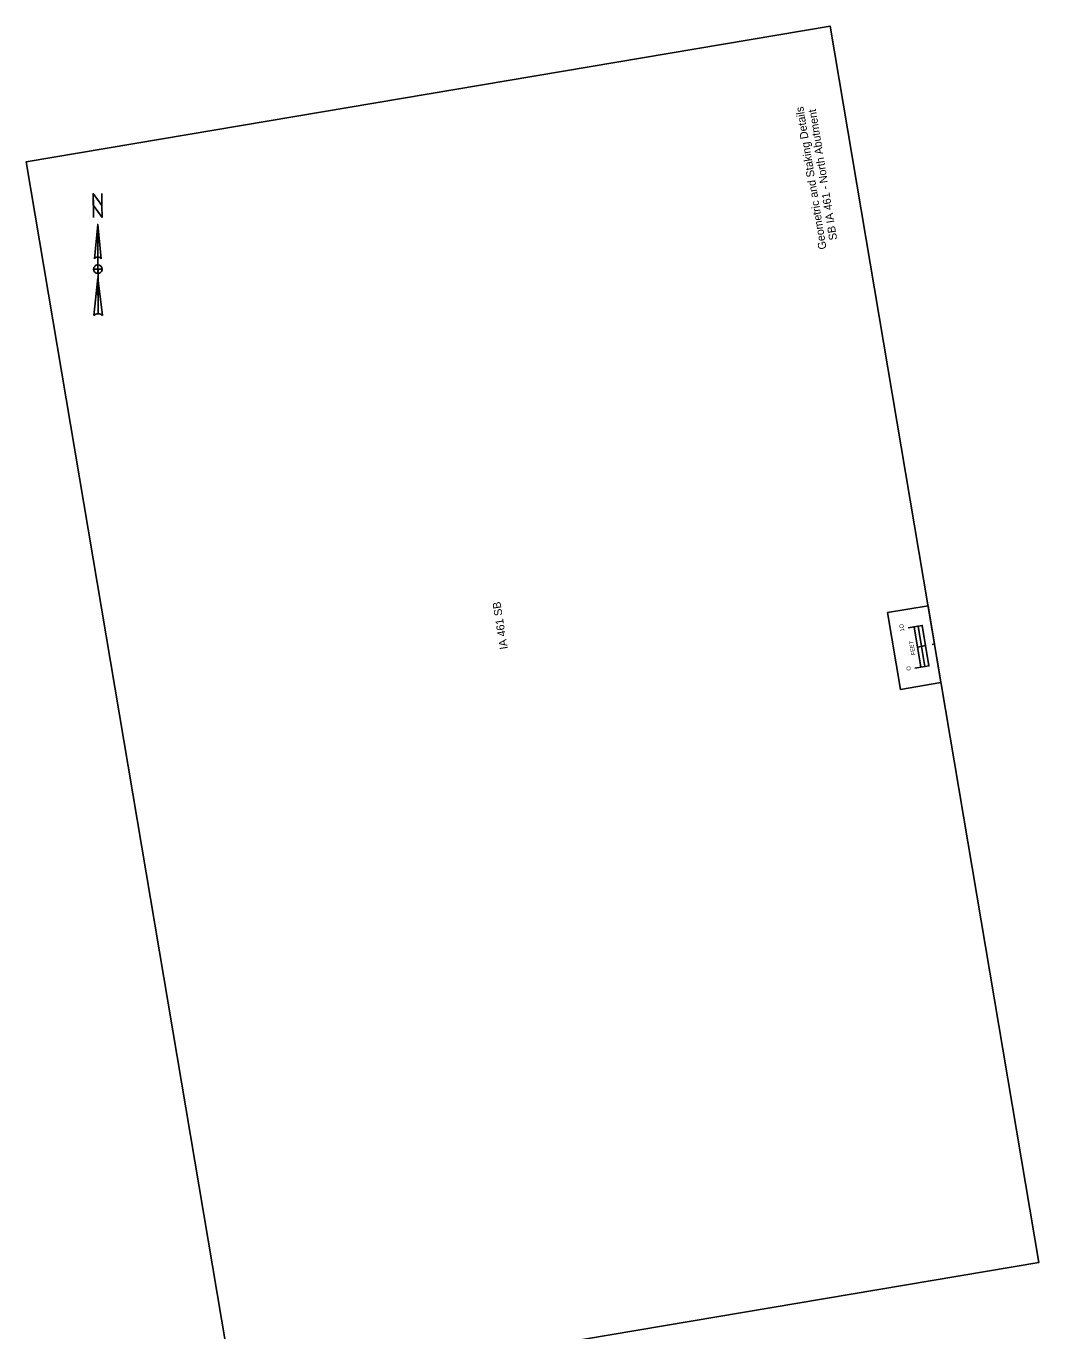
# Model space of a CAD drawing. Extents: x 21487943 to 21488253, y 8075016 to 8075692.
# Drawn here: x 21487943.4 to 21488196.6, y 8075365.9 to 8075692.1 of the extents above; entities that cross this region are included whole.
import ezdxf

# ---------------------------------------------------------------- set-up
doc = ezdxf.new("R2010")
doc.units = 0
for name, color, linetype in [('Default', 7, 'Continuous'), ('dsnCellElements', 7, 'Continuous'), ('dsnCellsScaleBlock', 7, 'Continuous'), ('dsnTextRoadwayLabel', 7, 'Continuous'), ('Level 20', 7, 'Continuous'), ('NamedBoundary', 7, 'Continuous')]:
    doc.layers.add(name, color=color, linetype=linetype)

msp = doc.modelspace()

# ---------------------------------------------------------------- linework, layer by layer
at = {"layer": 'Default'}
msp.add_line((21488170.46, 8075537.59), (21488169.86, 8075537.49), dxfattribs=at)
at = {"layer": 'dsnCellElements'}
for p, q in [((21487961.29, 8075642.51), (21487962.19, 8075633.93)), ((21487961.29, 8075642.51), (21487961.39, 8075620.2)), ((21487960.47, 8075633.92), (21487960.47, 8075633.92)), ((21487960.5, 8075634), (21487960.66, 8075634.18)), ((21487960.32, 8075619.76), (21487961.35, 8075629.21)), ((21487961.35, 8075630.28), (21487961.35, 8075630.28))]:
    msp.add_line(p, q, dxfattribs=at)
for points in [[(21487960.21, 8075644.22), (21487960.19, 8075650.22), (21487962.35, 8075647.23), (21487962.33, 8075650.23)], [(21487960.47, 8075633.92), (21487961.29, 8075642.51), (21487961.33, 8075634.36)], [(21487962.41, 8075631.36), (21487961.34, 8075631.35), (21487961.34, 8075632.42)], [(21487961.35, 8075630.28), (21487961.34, 8075631.35), (21487960.27, 8075631.35)], [(21487961.39, 8075620.2), (21487961.35, 8075629.21), (21487962.46, 8075619.77)]]:
    msp.add_lwpolyline(points, dxfattribs=at)
for points in [[(21487962.36, 8075644.23), (21487960.2, 8075647.22), (21487960.19, 8075650.22), (21487962.35, 8075647.23)], [(21488161.96, 8075526.29), (21488158.74, 8075545.5), (21488168.85, 8075547.19), (21488172.07, 8075527.99)]]:
    msp.add_lwpolyline(points, close=True, dxfattribs=at)
for centre, radius, start, end in [((21487961.34, 8075631.35), 1.07, 90.2458, 180.2458), ((21487961.33, 8075633.28), 1.07, 90.2662, 143.3715), ((21487961.33, 8075633.28), 1.07, 37.0938, 90.2676), ((21487961.34, 8075631.35), 1.07, 0.2458, 90.2458), ((21487961.34, 8075631.35), 1.07, 180.2458, 270.2458), ((21487961.34, 8075631.35), 1.07, 270.2458, 0.2458), ((21487961.4, 8075618.64), 1.55, 90.2352, 133.8647), ((21487961.4, 8075618.64), 1.56, 46.6478, 90.2464)]:
    msp.add_arc(centre, radius, start, end, dxfattribs=at)
at = {"layer": 'dsnCellsScaleBlock'}
msp.add_line((21488168.24, 8075537.22), (21488166.21, 8075536.88), dxfattribs=at)
msp.add_line((21488168.24, 8075537.22), (21488166.21, 8075536.88), dxfattribs=at)
for points in [[(21488172.07, 8075527.99), (21488161.96, 8075526.29), (21488158.74, 8075545.5), (21488168.85, 8075547.19)], [(21488167.22, 8075537.05), (21488166.37, 8075542.1), (21488165.37, 8075541.93), (21488166.21, 8075536.88)], [(21488169.08, 8075532.16), (21488168.24, 8075537.22), (21488167.22, 8075537.05), (21488168.07, 8075531.99)]]:
    msp.add_lwpolyline(points, close=True, dxfattribs=at)
for points in [[(21488165.55, 8075531.57), (21488169.08, 8075532.16), (21488167.39, 8075542.27), (21488163.85, 8075541.68)], [(21488167.06, 8075531.83), (21488165.37, 8075541.93)]]:
    msp.add_lwpolyline(points, dxfattribs=at)
at = {"layer": 'NamedBoundary'}
msp.add_lwpolyline([(21487995.59, 8075349.08), (21488196.57, 8075383.03), (21488144.36, 8075692.1), (21487943.38, 8075658.16)], close=True, dxfattribs=at)

# ---------------------------------------------------------------- texts
at = {"layer": 'dsnCellsScaleBlock'}
for s, height, p in [('1O', 1.025, (21488162.95, 8075540.85)), ('FEET', 1.025, (21488165.71, 8075534.93)), ('O', 1.02, (21488164.59, 8075531.07))]:
    msp.add_text(s, height=height, rotation=99.5277, dxfattribs=at).set_placement(p)
at = {"layer": 'dsnTextRoadwayLabel'}
msp.add_text('IA 461 SB', height=2, rotation=98.9826, dxfattribs=at).set_placement((21488063.81, 8075536.45))
at = {"layer": 'Level 20'}
for s, p in [('Geometric and Staking Details', (21488143.49, 8075636.44)), ('SB IA 461 - North Abutment', (21488146.15, 8075638.75))]:
    msp.add_text(s, height=2, rotation=99.2873, dxfattribs=at).set_placement(p)

doc.saveas('drawing.dxf')
